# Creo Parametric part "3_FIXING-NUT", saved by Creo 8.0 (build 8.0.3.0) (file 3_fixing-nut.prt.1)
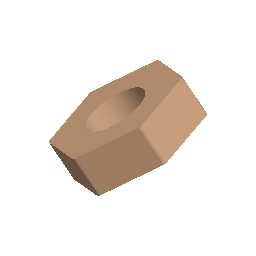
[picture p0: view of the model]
Units: millimeter Newton Second (mmNs); MM, TONNE, SECS

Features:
  1. datum plane "RIGHT"
  2. datum plane "TOP"
  3. datum plane "FRONT"
  4. coordinate system
  5. protrusion
  6. cut
  7. round

Layers: 0_ALL_AXIS, 0_ALL_CSYS, 0_ALL_CURVES, 0_ALL_PLANES, 0_ALL_POINTS, 0_ALL_SURFS, FIXING-NUT

Surfaces: 8 plane, 7 cylinder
